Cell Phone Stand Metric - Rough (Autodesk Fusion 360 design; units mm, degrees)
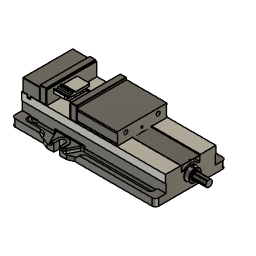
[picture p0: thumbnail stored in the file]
description: HaasClamp
derived_base_feature "Derived Base Feature" bodies "Stand Body"
align "Align1"
base_feature "Base Feature1"
base_feature "Base Feature1"
base_feature "Base Feature1"
base_feature "Base Feature1"
base_feature "Base Feature1"
base_feature "Base Feature1"
base_feature "Base Feature1"
base_feature "Base Feature1"
base_feature "Base Feature1"
base_feature "Base Feature1"
as_built_joint "As-built1"
as_built_joint "As-built2"
as_built_joint "As-built3"
joint_origin "JointOrigin1" OffsetX 0 OffsetY 0 OffsetZ 0 AngleZ 0
joint "Assemble1" alignAngle 180 alignOffsetX 0 alignOffsetY 0 alignOffsetZ 0 (= "jaw_width_haas_050002") SlideMaximum 22.5 SlideMinimum 0
position "Position1"
sketch "Sketch1" plane through (0, -72.5, 0) normal (0, -1, 0) x axis (1, 0, 0)
  line L1 (75, 73) -> (-75, 73)
  line L2 (76, 74) -> (75, 73)
  line L3 (76, 116.5) -> (76, 74)
  line L4 (75, 117.5) -> (76, 116.5)
  line L5 (-75, 117.5) -> (75, 117.5)
  line L6 (-76, 116.5) -> (-75, 117.5)
  line L7 (-76, 74) -> (-76, 116.5)
  line L8 (-75, 73) -> (-76, 74)
  line L9 (76.4, 114.275) -> (-76, 114.275)
  line L10 (76.4, 73) -> (76.4, 114.275)
  line L11 (-76, 73) -> (76.4, 73)
  line L12 (-76, 114.275) -> (-76, 73)
  circle C1 centre (49.21, 96.8) radius 11
  circle C2 centre (-49.21, 96.8) radius 11
  point P14 (76.4, 73)
  point P12 (-76, 114.275)
  point P13 (76.4, 114.275)
  horizontal L9
  vertical L10
  horizontal L11
  vertical L12
  coincident L1 P14
  coincident L7 P12
  dimension "d16" distance P12 P13 = 152.4
  dimension "d17" distance P13 P14 = 41.275
place_component sketch "Sketch1"
extrude "Extrude1" new body sketch "Sketch1" profile of L1 L2 L3 L7 L8 C1 C2 L9 L11 L12 along normal blind 3.175
place_component sketch "Sketch1"
extrude "Extrude1" sketch "Sketch1" profile of L1 L2 L3 L7 L8 C1 C2 L9 L11 L12 blind -3.175
as_built_joint "As-built5"
as_built_joint "As-built6"
sketch "Sketch1" plane through (0, 0, 0) normal (0, 0, -1) x axis (1, 0, 0)
  line L1 (16.5, -37.5) -> (-16.5, -37.5)
  line L2 (20, 34) -> (20, -34)
  line L3 (-16.5, 37.5) -> (16.5, 37.5)
  line L4 (-20, -34) -> (-20, 34)
  line L5 (-38.1, -40) -> (38.1, -40)
  line L6 (-38.1, 40) -> (-38.1, -40)
  line L7 (38.1, 40) -> (-38.1, 40)
  line L8 (38.1, -40) -> (38.1, 40)
  line L9 (-38.1, 40) -> (38.1, -40)
  line L10 (38.1, 40) -> (-38.1, -40)
  arc A1 centre (-16.5, -34) radius 3.5 clockwise from (-16.5, -37.5) to (-20, -34)
  arc A2 centre (16.5, -34) radius 3.5 clockwise from (20, -34) to (16.5, -37.5)
  arc A3 centre (16.5, 34) radius 3.5 clockwise from (16.5, 37.5) to (20, 34)
  arc A4 centre (-16.5, 34) radius 3.5 clockwise from (-20, 34) to (-16.5, 37.5)
  point P18 (0, 0)
  point P1 (0, 0)
  point P16 (-38.1, 40)
  point P17 (38.1, 40)
  point P15 (-38.1, -40)
  horizontal L5
  perpendicular L5 L6
  parallel L5 L7
  parallel L6 L8
  coincident L9 P18
  coincident L10 P18
  coincident P1 P18
  dimension "d1" distance P16 P17 = 76.2
  dimension "d2" distance P15 P16 = 80
extrude "Extrude1" new body sketch "Sketch1" profile of A1 L1 A2 L2 A3 L3 A4 L4 L5 L6 L7 L8 against normal blind 10 bodies "Stock"
position "Position1"
ground "Pin"
position "Position2"
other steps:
create_component "CreateComponent1"
create_component "CreateComponent2"
create_component "CreateComponent3"
create_component "CreateComponent4"
create_component "CreateComponent5"
create_component "CreateComponent6"
create_component "CreateComponent7"
create_component "CreateComponent8"
create_component "CreateComponent9"
create_component "CreateComponent10"
joint_origin "JointOrigin10"
joint_origin "JointOrigin11"
create_component "CreateComponent11" sketch "Sketch1"
create_component "CreateComponent12" sketch "Sketch1"
create_component "CreateComponent1"
named bodies: "Stand Body", "Stock"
